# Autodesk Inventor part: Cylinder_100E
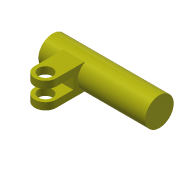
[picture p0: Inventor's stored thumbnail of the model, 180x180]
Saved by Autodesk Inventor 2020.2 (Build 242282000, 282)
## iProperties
Created: 2005-10
Part Number: Cylinder_100E
Document SubType Name: Modeling
Designer: F.Stasiak
Density: 1 g/cm^3
Material: Ogólny
Appearance: Żółta
Manager: www.cadconsulting.pl
Company: Fabian Stasiak CAD Consulting
Author: F.Stasiak
Subject: Zbiór ćwiczeń. Autodesk Inventor 2020. Kurs podstawowy
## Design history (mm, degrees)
sketch "Szkic1"
  geometry: L1 (315.334, 20)-(315.334, 40); L2 (315.334, 40)-(330.334, 40); L3 (330.334, 40)-(330.334, 20); C1 r 5 at (322.834, 20) reference; A1 r 7.5 centre (322.834, 20) between (315.334, 20) and (330.334, 20)
  constraints: 6 end point, 2 point on circle, 2 tangent, 1 centre point, 1 coincident, 1 perpendicular, 1 vertical
  dimensions: "d0" = 15 diameter of A1; "d1" = 15 distance of L1.end L2.end; "d2" = 20 distance of L2.end L3.end
extrude "Wyciągnięcie proste1" new body sketch "Szkic1" stored distance "d3" = 18; taper "d4" = 0 deg
sketch "Szkic2"
  geometry: L1 (315.334, 20)-(315.334, 32); L2 (315.334, 32)-(330.334, 32); L3 (330.334, 32)-(330.334, 20); C1 r 5 at (322.834, 20) reference; A1 r 7.5 centre (322.834, 20) between (315.334, 20) and (330.334, 20) reference
  constraints: 6 end point, 2 tangent, 1 parallel, 1 perpendicular, 1 vertical
  dimensions: "d5" = 12 distance from line of C1.centre L2
extrude "Wyciągnięcie proste2" cut sketch "Szkic2" stored distance "d6" = 8; taper "d7" = 0 deg
node "Płaszczyzna konstrukcyjna1"
sketch "Szkic3"
  geometry: L1 (0, -18)-(0, 0) reference; L2 (0, -9)-(5, -9); C1 r 10 at (5, -9)
  constraints: 2 end point, 1 centre point, 1 midpoint, 1 perpendicular
  dimensions: "d8" = 20 diameter of C1; "d9" = 5 distance of L2.start L2.end
extrude "Wyciągnięcie proste3" join sketch "Szkic3" stored distance "d10" = 40; taper "d11" = 0 deg
sketch "Szkic4"
  geometry: C1 r 10 at (0, 0) reference
extrude "Wyciągnięcie proste7" join sketch "Szkic4" distance "d19" = 35; taper "d20" = 0 deg
sketch "Szkic7"
  geometry: C1 r 10 at (0, 0) reference; C2 r 5 at (0, 0); 1 further point
  constraints: 1 centre point, 1 coincident
  dimensions: "d21" = 10 diameter of C2
extrude "Wyciągnięcie proste8" cut sketch "Szkic7" distance "d22" = 70; taper "d23" = 0 deg
node "Bryła1"
node "Korpusy bryłowe"
node "Korpusy powierzchniowe"
node "Odniesienie1"
node "Pętla rzutowana1"
